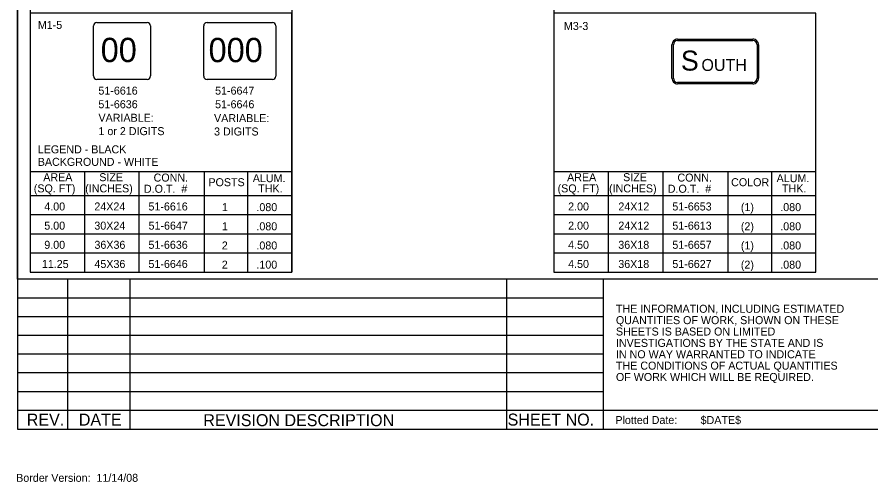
# Model space of a CAD drawing. Extents: x 0 to 2011, y -71 to 1183.
# Drawn here: x -0.1 to 341.3, y -22.1 to 164 of the extents above; entities that cross this region are included whole.
import ezdxf

# ---------------------------------------------------------------- set-up
doc = ezdxf.new("R2010")
doc.units = 0
for name, color, linetype in [('CT_Border_Perimeter_Shape', 7, 'Continuous'), ('CT_Construction', 7, 'Continuous'), ('CT_Disclaimer_Text', 7, 'Continuous'), ('CT_Locked', 7, 'Continuous'), ('CT_Title_Block_Linework', 7, 'Continuous'), ('CT_Title_Block_Text', 7, 'Continuous'), ('Level 1', 7, 'Continuous'), ('Level 10', 7, 'Continuous'), ('Level 2', 7, 'Continuous'), ('Level 22', 7, 'Continuous'), ('Level 5', 7, 'Continuous')]:
    doc.layers.add(name, color=color, linetype=linetype)

msp = doc.modelspace()

# ---------------------------------------------------------------- linework, layer by layer
at = {"layer": 'CT_Border_Perimeter_Shape'}
msp.add_lwpolyline([(0, -0.97), (1270, -0.97), (1270, 829.03), (0, 829.03)], close=True, dxfattribs=at)
at = {"layer": 'CT_Construction'}
msp.add_lwpolyline([(0, 829.03), (1270, 829.03), (1270, 59.03), (0, 59.03)], close=True, dxfattribs=at)
at = {"layer": 'CT_Locked'}
msp.add_line((0, -0.97), (0, -0.97), dxfattribs=at)
at = {"layer": 'CT_Title_Block_Linework'}
for p, q in [((1270, 59.03), (0, 59.03)), ((20, 59.03), (20, -0.97)), ((45, 59.03), (45, -0.97)), ((195.61, 59.03), (195.61, -0.97)), ((234.31, 59.03), (234.31, -0.97)), ((234.31, 51.53), (0, 51.53)), ((234.31, 44.03), (0, 44.03)), ((234.31, 36.53), (0, 36.53)), ((234.31, 29.03), (0, 29.03)), ((234.31, 21.53), (0, 21.53)), ((234.31, 14.03), (0, 14.03)), ((344.55, 6.53), (0, 6.53))]:
    msp.add_line(p, q, dxfattribs=at)
at = {"layer": 'Level 1'}
for p, q in [((264.01, 155.12), (294.13, 155.12)), ((264.01, 154.55), (294.13, 154.55)), ((261.77, 139.49), (261.77, 152.87)), ((262.34, 139.49), (262.34, 152.87)), ((295.8, 152.87), (295.8, 139.49)), ((296.37, 152.87), (296.37, 139.49)), ((294.13, 137.81), (264.01, 137.81)), ((294.13, 137.24), (264.01, 137.24))]:
    msp.add_line(p, q, dxfattribs=at)
for centre, radius, start, end in [((264.01, 152.87), 2.24, 90, 180.0015), ((264.01, 152.87), 1.67, 90, 180), ((294.13, 152.87), 2.24, 359.9993, 90), ((294.13, 152.87), 1.67, 0, 90), ((264.01, 139.49), 2.24, 179.998, 270), ((264.01, 139.49), 1.67, 180, 270), ((294.13, 139.49), 1.67, 270, 360), ((294.13, 139.49), 2.24, 270, 0.0005)]:
    msp.add_arc(centre, radius, start, end, dxfattribs=at)
at = {"layer": 'Level 10'}
for points in [[(31.77, 161.82), (51.82, 161.82)], [(75.89, 161.79), (101.96, 161.79)], [(30.38, 140.38), (30.38, 160.43)], [(53.21, 160.43), (53.21, 140.38)], [(74.5, 140.35), (74.5, 160.4)], [(103.35, 160.4), (103.35, 140.35)], [(51.82, 138.99), (31.77, 138.99)], [(101.96, 138.97), (75.89, 138.97)]]:
    msp.add_lwpolyline(points, dxfattribs=at)
for centre, start, end in [((31.77, 160.43), 90, 180), ((51.82, 160.43), 0, 90), ((75.89, 160.4), 90, 180), ((101.96, 160.4), 0, 90), ((31.77, 140.38), 180, 270), ((51.82, 140.38), 270, 360), ((75.89, 140.35), 180, 270), ((101.96, 140.35), 270, 360)]:
    msp.add_arc(centre, 1.39, start, end, dxfattribs=at)
at = {"layer": 'Level 2'}
for p, q in [((5.05, 102.16), (109.8, 102.16)), ((26.8, 102.16), (26.8, 61.88)), ((48.55, 102.16), (48.55, 61.88)), ((74.65, 102.16), (74.65, 61.88)), ((92.05, 102.16), (92.05, 61.88)), ((214.55, 102.16), (319.3, 102.16)), ((236.3, 102.16), (236.3, 61.88)), ((258.05, 102.16), (258.05, 61.88)), ((284.15, 102.16), (284.15, 61.88)), ((301.55, 102.16), (301.55, 61.88)), ((5.05, 92.57), (109.8, 92.57)), ((214.55, 92.57), (319.3, 92.57)), ((5.05, 84.9), (109.8, 84.9)), ((214.55, 84.9), (319.3, 84.9)), ((5.05, 77.22), (109.8, 77.22)), ((214.55, 77.22), (319.3, 77.22)), ((5.05, 69.55), (109.8, 69.55)), ((214.55, 69.55), (319.3, 69.55))]:
    msp.add_line(p, q, dxfattribs=at)
for points in [[(109.8, 165.5), (5.05, 165.5), (5.05, 61.88), (109.8, 61.88)], [(319.3, 165.5), (214.55, 165.5), (214.55, 61.88), (319.3, 61.88)]]:
    msp.add_lwpolyline(points, close=True, dxfattribs=at)
at = {"layer": 'Level 5'}
for p, q in [((5.05, 391.26), (5.05, 61.88)), ((109.8, 391.26), (109.8, 61.88)), ((214.55, 391.26), (214.55, 61.88))]:
    msp.add_line(p, q, dxfattribs=at)

# ---------------------------------------------------------------- texts
at = {"layer": 'CT_Disclaimer_Text'}
for s, p in [('THE INFORMATION, INCLUDING ESTIMATED ', (239.35, 45.62)), ('QUANTITIES OF WORK, SHOWN ON THESE ', (239.35, 41.07)), ('SHEETS IS BASED ON LIMITED ', (239.35, 36.52)), ('INVESTIGATIONS BY THE STATE AND IS', (239.35, 31.97)), ('IN NO WAY WARRANTED TO INDICATE ', (239.35, 27.42)), ('THE CONDITIONS OF ACTUAL QUANTITIES ', (239.35, 22.87)), ('OF WORK WHICH WILL BE REQUIRED.', (239.35, 18.32))]:
    msp.add_text(s, height=3.2, rotation=360, dxfattribs=at).set_placement(p)
at = {"layer": 'CT_Title_Block_Text'}
for s, height, rotation, p in [('REV.', 4.8, 360, (3.73, 0.45)), ('DATE', 4.8, 360, (24.55, 0.45)), ('REVISION DESCRIPTION', 4.8, 360, (74.34, 0.24)), ('SHEET NO.', 4.8, 360, (196.03, 0.47)), ('Plotted Date:', 3.2, 0.125, (239.14, 1.08)), ('$DATE$', 3.2, 0.125, (273.22, 1.07)), ('Border Version:  11/14/08', 3.2, 360, (-0.5, -22.04))]:
    msp.add_text(s, height=height, rotation=rotation, dxfattribs=at).set_placement(p)
at = {"layer": 'Level 1'}
msp.add_text('S', height=8, dxfattribs=at).set_placement((265.34, 142.54))
at = {"layer": 'Level 2'}
for s, height, p in [('M1-5', 3.2, (8.15, 159.22)), ('M3-3', 3.2, (218.55, 158.79)), ('OUTH', 4.8, (273.55, 142.39)), ('51-6616', 3.2, (32.38, 132.92)), ('51-6647', 3.2, (79.05, 132.92)), ('51-6636', 3.2, (32.38, 127.47)), ('51-6646', 3.2, (79.05, 127.47)), ('VARIABLE: ', 3.2, (32.4, 122.07)), ('VARIABLE: ', 3.2, (78.63, 121.93)), ('1 or 2 DIGITS', 3.2, (32.4, 116.71)), ('3 DIGITS', 3.2, (78.63, 116.57)), ('LEGEND - BLACK', 3.2, (8.13, 109.42)), ('BACKGROUND - WHITE', 3.2, (8.13, 104.42)), ('AREA', 3.2, (10.32, 98.28)), ('SIZE', 3.2, (32.73, 98.28)), ('CONN.', 3.2, (54.45, 98.12)), ('POSTS', 3.2, (76.38, 96.27)), ('ALUM.', 3.2, (94.12, 97.89)), ('AREA', 3.2, (219.82, 98.28)), ('SIZE', 3.2, (242.23, 98.28)), ('CONN.', 3.2, (263.95, 98.12)), ('COLOR', 3.2, (285.42, 96.27)), ('ALUM.', 3.2, (303.61, 97.89)), ('(SQ. FT)', 3.2, (6.54, 93.8)), ('(INCHES)', 3.2, (27.1, 93.8)), ('D.O.T.  #', 3.2, (50.59, 93.65)), ('THK.', 3.2, (96.29, 93.76)), ('(SQ. FT)', 3.2, (216.03, 93.8)), ('(INCHES)', 3.2, (236.6, 93.8)), ('D.O.T.  #', 3.2, (260.08, 93.65)), ('THK.', 3.2, (305.79, 93.76))]:
    msp.add_text(s, height=height, dxfattribs=at).set_placement(p)
at = {"layer": 'Level 22'}
for s, p in [('00', (33.29, 145.94)), ('000', (76.43, 145.91))]:
    msp.add_text(s, height=9.72, dxfattribs=at).set_placement(p)
at = {"layer": 'Level 5'}
for s, p in [(' 4.00', (9.55, 86.56)), ('24X24', (30.76, 86.56)), ('51-6616', (52.4, 86.56)), ('1', (81.79, 86.3)), ('.080', (95.57, 86.3)), (' 2.00', (219.05, 86.56)), ('24X12', (240.32, 86.56)), ('51-6653', (261.92, 86.56)), ('(1)', (289.31, 86.3)), ('.080', (305.07, 86.3)), (' 5.00', (9.55, 78.89)), ('30X24', (30.76, 78.89)), ('51-6647', (52.43, 78.89)), (' 2.00', (219.05, 78.89)), ('24X12', (240.32, 78.89)), ('51-6613', (261.92, 78.89)), ('(2)', (289.31, 78.63)), ('1', (81.79, 78.63)), ('.080', (95.57, 78.63)), ('.080', (305.07, 78.63)), (' 9.00', (9.55, 71.22)), ('36X36', (30.79, 71.22)), ('51-6636', (52.4, 71.22)), ('2', (81.73, 70.96)), ('.080', (95.57, 70.96)), (' 4.50', (219.05, 71.22)), ('36X18', (240.29, 71.22)), ('51-6657', (261.92, 71.22)), ('(1)', (289.31, 70.96)), ('.080', (305.07, 70.96)), ('11.25', (9.77, 63.55)), ('45X36', (30.79, 63.55)), ('51-6646', (52.4, 63.55)), ('2', (81.73, 63.28)), ('.100', (95.57, 63.28)), (' 4.50', (219.05, 63.55)), ('36X18', (240.29, 63.55)), ('51-6627', (261.92, 63.55)), ('(2)', (289.31, 63.28)), ('.080', (305.07, 63.28))]:
    msp.add_text(s, height=3.2, dxfattribs=at).set_placement(p)

doc.saveas('drawing.dxf')
